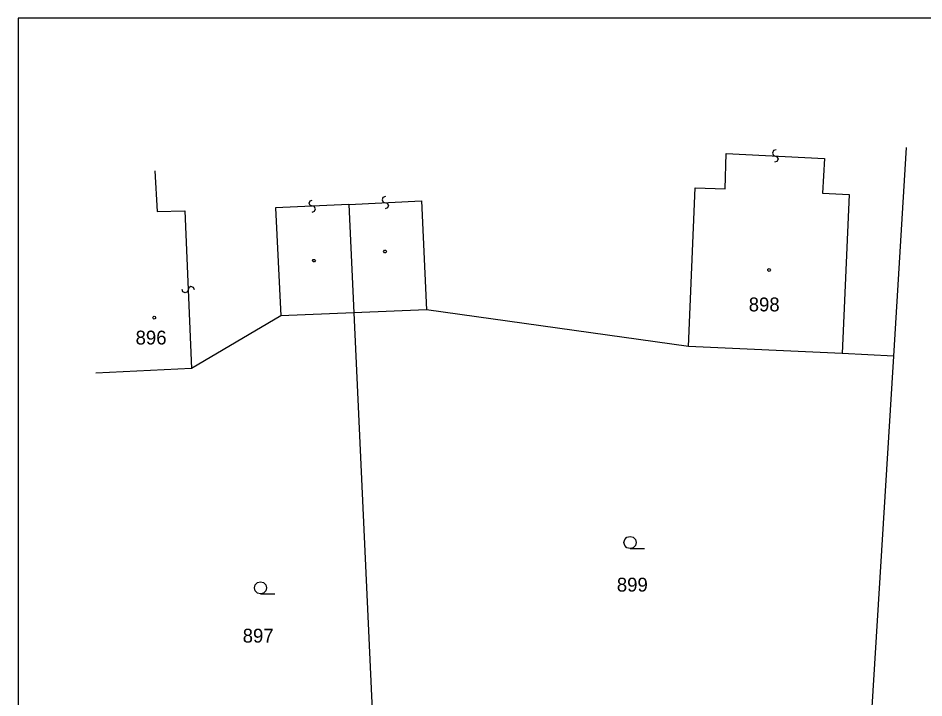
# Model space of a CAD drawing. Extents: x -456675 to -456278, y -1112395 to -1112217.
# Drawn here: x -456383.2 to -456327.7, y -1112266.8 to -1112225.2 of the extents above; entities that cross this region are included whole.
import ezdxf

# ---------------------------------------------------------------- set-up
doc = ezdxf.new("R2010")
doc.units = 0
doc.layers.add('Katastralni_mapa', color=7, linetype='Continuous')
doc.layers.add('Ramecek-tisk', color=7, linetype='Continuous')

msp = doc.modelspace()

# ---------------------------------------------------------------- linework, layer by layer
at = {"layer": 'Katastralni_mapa'}
for points in [[(-456336.779, -1112233.267), (-456336.931, -1112233.309), (-456336.999, -1112233.461), (-456336.936, -1112233.599), (-456336.701, -1112233.697), (-456336.649, -1112233.839), (-456336.726, -1112233.981), (-456336.868, -1112234.013)], [(-456328.808, -1112233.12), (-456329.593, -1112245.9)], [(-456339.893, -1112235.64), (-456339.833, -1112233.48)], [(-456339.833, -1112233.48), (-456333.813, -1112233.8)], [(-456333.813, -1112233.8), (-456333.923, -1112235.92)], [(-456374.843, -1112234.54), (-456374.693, -1112237.04)], [(-456342.153, -1112245.31), (-456341.743, -1112235.58)], [(-456341.743, -1112235.58), (-456339.893, -1112235.64)], [(-456333.923, -1112235.92), (-456332.303, -1112235.99)], [(-456332.303, -1112235.99), (-456332.723, -1112245.73)], [(-456365.205, -1112237.086), (-456365.058, -1112237.028), (-456365.005, -1112236.871), (-456365.082, -1112236.739), (-456365.326, -1112236.666), (-456365.392, -1112236.529), (-456365.33, -1112236.381), (-456365.192, -1112236.334)], [(-456362.953, -1112236.6), (-456358.493, -1112236.38)], [(-456360.717, -1112236.114), (-456360.864, -1112236.172), (-456360.917, -1112236.329), (-456360.84, -1112236.461), (-456360.596, -1112236.534), (-456360.529, -1112236.671), (-456360.592, -1112236.819), (-456360.73, -1112236.866)], [(-456358.493, -1112236.38), (-456358.203, -1112243.06)], [(-456374.693, -1112237.04), (-456372.993, -1112237)], [(-456372.993, -1112237), (-456372.593, -1112246.66)], [(-456362.953, -1112236.6), (-456367.443, -1112236.82)], [(-456367.443, -1112236.82), (-456367.123, -1112243.44)], [(-456362.953, -1112236.6), (-456362.653, -1112243.25)], [(-456372.418, -1112241.84), (-456372.474, -1112241.692), (-456372.631, -1112241.638), (-456372.763, -1112241.714), (-456372.838, -1112241.957), (-456372.976, -1112242.023), (-456373.123, -1112241.959), (-456373.169, -1112241.82)], [(-456362.653, -1112243.25), (-456367.123, -1112243.44)], [(-456358.203, -1112243.06), (-456362.653, -1112243.25)], [(-456362.653, -1112243.25), (-456361.433, -1112269.37)], [(-456342.153, -1112245.31), (-456358.203, -1112243.06)], [(-456367.123, -1112243.44), (-456372.593, -1112246.66)], [(-456332.723, -1112245.73), (-456342.153, -1112245.31)], [(-456329.593, -1112245.9), (-456332.723, -1112245.73)], [(-456329.593, -1112245.9), (-456330.953, -1112268.06)], [(-456372.593, -1112246.66), (-456378.444, -1112246.954)], [(-456345.723, -1112257.697), (-456345.913, -1112257.647), (-456346.048, -1112257.507), (-456346.098, -1112257.322), (-456346.048, -1112257.137), (-456345.913, -1112256.997), (-456345.723, -1112256.947), (-456345.533, -1112256.997), (-456345.398, -1112257.137), (-456345.348, -1112257.322), (-456345.398, -1112257.507), (-456345.533, -1112257.647), (-456345.723, -1112257.697), (-456344.848, -1112257.697)], [(-456368.364, -1112260.475), (-456368.554, -1112260.425), (-456368.689, -1112260.285), (-456368.739, -1112260.1), (-456368.689, -1112259.915), (-456368.554, -1112259.775), (-456368.364, -1112259.725), (-456368.174, -1112259.775), (-456368.039, -1112259.915), (-456367.989, -1112260.1), (-456368.039, -1112260.285), (-456368.174, -1112260.425), (-456368.364, -1112260.475), (-456367.489, -1112260.475)]]:
    msp.add_lwpolyline(points, dxfattribs=at)
for points in [[(-456360.688, -1112239.415), (-456360.643, -1112239.49), (-456360.688, -1112239.565), (-456360.778, -1112239.565), (-456360.823, -1112239.49), (-456360.778, -1112239.415)], [(-456365.048, -1112239.975), (-456365.003, -1112240.05), (-456365.048, -1112240.125), (-456365.138, -1112240.125), (-456365.183, -1112240.05), (-456365.138, -1112239.975)], [(-456337.205, -1112240.537), (-456337.155, -1112240.547), (-456337.13, -1112240.592), (-456337.12, -1112240.622), (-456337.13, -1112240.667), (-456337.17, -1112240.702), (-456337.205, -1112240.707), (-456337.25, -1112240.692), (-456337.28, -1112240.662), (-456337.29, -1112240.622), (-456337.28, -1112240.577), (-456337.24, -1112240.542)], [(-456374.876, -1112243.458), (-456374.826, -1112243.468), (-456374.801, -1112243.513), (-456374.791, -1112243.543), (-456374.801, -1112243.588), (-456374.841, -1112243.623), (-456374.876, -1112243.628), (-456374.921, -1112243.613), (-456374.951, -1112243.583), (-456374.961, -1112243.543), (-456374.951, -1112243.498), (-456374.911, -1112243.463)]]:
    msp.add_lwpolyline(points, close=True, dxfattribs=at)
at = {"layer": 'Ramecek-tisk'}
msp.add_lwpolyline([(-456383.215, -1112373.688), (-456278.215, -1112373.688), (-456278.215, -1112225.188), (-456383.215, -1112225.188)], close=True, dxfattribs=at)

# ---------------------------------------------------------------- texts
at = {"layer": 'Katastralni_mapa'}
for s, p in [('898', (-456338.454, -1112243.16)), ('896', (-456376.019, -1112245.19)), ('899', (-456346.534, -1112260.33)), ('897', (-456369.457, -1112263.457))]:
    msp.add_text(s, height=0.85, dxfattribs=at).set_placement(p)

doc.saveas('drawing.dxf')
